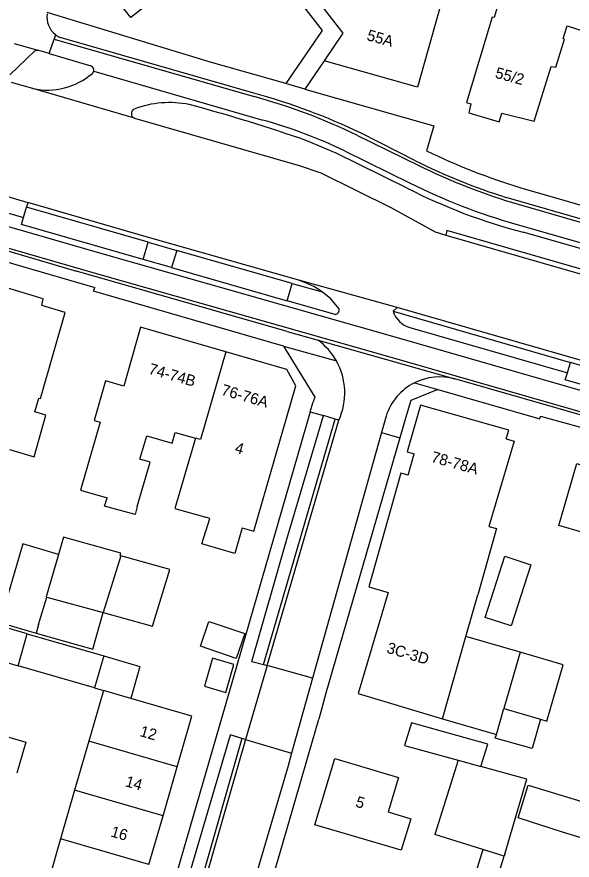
# Model space of a CAD drawing. Extents: x 194485 to 197793, y 468269 to 470822.
# Drawn here: x 195024.7 to 195084.7, y 469884.3 to 469975.4 of the extents above; entities that cross this region are included whole.
import ezdxf

# ---------------------------------------------------------------- set-up
doc = ezdxf.new("R2010")
doc.units = 0
for name, color, linetype in [('BGT grensvlak gebouwinstallatie plus 1', 7, 'Continuous'), ('BGT grensvlak ondersteunend wegdeel', 7, 'Continuous'), ('BGT grensvlak overig bouwwerk uitbreiding populatie', 7, 'Continuous'), ('BGT grensvlak pand op maaiveld', 7, 'Continuous'), ('BGT grensvlak pand op maaiveld LR', 7, 'Continuous'), ('BGT grensvlak vegetatieobject', 7, 'Continuous'), ('BGT grensvlak wegdeel', 7, 'Continuous'), ('BGT tekst huisnummerreeks', 7, 'Continuous')]:
    doc.layers.add(name, color=color, linetype=linetype)

msp = doc.modelspace()

# ---------------------------------------------------------------- linework, layer by layer
at = {"layer": 'BGT grensvlak gebouwinstallatie plus 1'}
for p, q in [((195079.063, 469906.728), (195073.22, 469908.419)), ((195079.063, 469906.728), (195077.314, 469900.655)), ((195083.744, 469905.365), (195079.063, 469906.728)), ((195033.077, 469902.876), (195034.039, 469902.6)), ((195076.507, 469897.852), (195077.314, 469900.655)), ((195077.314, 469900.655), (195081.283, 469899.485)), ((195070.702, 469899.524), (195076.507, 469897.852)), ((195081.283, 469899.485), (195080.37, 469896.314)), ((195076.394, 469897.459), (195076.507, 469897.852)), ((195080.37, 469896.314), (195076.394, 469897.459)), ((195075.06, 469885.416), (195073.14, 469879.238)), ((195075.455, 469878.553), (195077.355, 469884.702))]:
    msp.add_line(p, q, dxfattribs=at)
for points in [[(195029.188, 469917.299), (195025.31, 469918.449), (195022.793, 469909.966), (195026.751, 469908.792)], [(195045.429, 469910.07), (195049.306, 469908.766), (195048.398, 469906.069), (195044.521, 469907.373), (195045.429, 469910.07)], [(195034.07, 469906.329), (195037.981, 469905.202), (195036.987, 469901.746)], [(195081.283, 469899.485), (195081.952, 469899.287), (195083.744, 469905.365)]]:
    msp.add_lwpolyline(points, dxfattribs=at)
at = {"layer": 'BGT grensvlak ondersteunend wegdeel'}
msp.add_line((195025.884, 469955.345), (195025.74, 469954.853), dxfattribs=at)
at = {"layer": 'BGT grensvlak overig bouwwerk uitbreiding populatie'}
for p, q in [((195045.83, 469906.081), (195044.957, 469903.056)), ((195048.134, 469905.417), (195045.83, 469906.081)), ((195047.262, 469902.392), (195048.134, 469905.417)), ((195044.957, 469903.056), (195047.262, 469902.392))]:
    msp.add_line(p, q, dxfattribs=at)
at = {"layer": 'BGT grensvlak pand op maaiveld'}
for p, q in [((195066.959, 469925.863), (195067.612, 469928.194)), ((195049.039, 469920.182), (195048.236, 469917.405)), ((195027.012, 469909.719), (195027.909, 469912.695)), ((195073.22, 469908.419), (195074.498, 469912.933)), ((195034.006, 469911.011), (195038.678, 469909.72)), ((195027.012, 469909.719), (195026.751, 469908.792)), ((195025.811, 469908.71), (195034.07, 469906.329)), ((195070.702, 469899.524), (195073.22, 469908.419)), ((195034.07, 469906.329), (195033.077, 469902.876)), ((195033.077, 469902.876), (195024.828, 469905.258)), ((195034.039, 469902.6), (195032.455, 469897.124)), ((195036.987, 469901.746), (195034.039, 469902.6)), ((195023.547, 469897.627), (195025.638, 469897.003)), ((195025.638, 469897.003), (195024.663, 469893.659)), ((195032.455, 469897.124), (195030.927, 469891.84)), ((195072.368, 469895.064), (195069.871, 469887.028)), ((195040.483, 469889.07), (195042.013, 469894.354)), ((195030.927, 469891.84), (195029.399, 469886.557)), ((195038.953, 469883.787), (195040.483, 469889.07)), ((195083.661, 469887.296), (195078.873, 469888.827)), ((195029.399, 469886.557), (195027.871, 469881.273)), ((195075.06, 469885.416), (195069.871, 469887.028)), ((195077.355, 469884.702), (195075.06, 469885.416)), ((195077.421, 469884.927), (195077.355, 469884.702))]:
    msp.add_line(p, q, dxfattribs=at)
for points in [[(195088.757, 469981.919), (195084.99, 469983.19), (195083.66, 469978.903), (195081.806, 469979.503), (195081.053, 469976.868), (195077.065, 469978.039), (195076.261, 469975.326), (195076.057, 469975.362), (195073.279, 469966.137), (195073.765, 469966.003), (195073.523, 469965.018), (195076.808, 469964.055), (195077.114, 469964.989), (195080.588, 469964.143), (195082.43, 469970.055), (195082.941, 469969.96), (195083.88, 469972.98), (195083.726, 469973.067), (195084.153, 469974.436), (195086.276, 469973.751), (195087.602, 469978.115)], [(195071.918, 469981.777), (195068.001, 469967.805), (195057.878, 469970.659)], [(195056.651, 469977.891), (195059.918, 469973.658), (195057.878, 469970.659)], [(195023.89, 469928.648), (195026.554, 469927.87), (195027.812, 469932.365), (195026.619, 469932.715), (195027.072, 469934.188), (195027.224, 469934.162), (195029.905, 469943.468), (195027.368, 469944.22), (195027.524, 469944.944), (195020.571, 469947.029), (195019.214, 469942.648)], [(195047.263, 469939.204), (195038.062, 469941.864), (195036.235, 469935.501), (195034.252, 469936.059), (195033.026, 469931.79), (195033.681, 469931.606), (195031.574, 469924.241), (195034.428, 469923.416)], [(195049.039, 469920.182), (195050.293, 469919.82), (195054.849, 469935.523), (195053.855, 469937.298), (195047.263, 469939.204)], [(195077.581, 469929.787), (195077.849, 469930.74), (195068.299, 469933.426), (195066.867, 469928.406), (195067.612, 469928.194)], [(195037.691, 469922.473), (195039.082, 469927.286), (195037.987, 469927.603), (195038.72, 469930.139), (195041.458, 469929.348), (195041.791, 469930.5), (195043.981, 469929.867)], [(195043.981, 469929.867), (195041.767, 469922.284), (195045.118, 469921.316)], [(195077.581, 469929.787), (195078.42, 469929.55), (195075.707, 469920.315), (195076.532, 469920.094), (195074.498, 469912.933)], [(195085.187, 469927.13), (195085.897, 469926.885), (195086.355, 469928.042), (195089.172, 469927.301), (195088.836, 469926.259), (195096.525, 469923.95), (195094.499, 469917.185), (195094.219, 469917.276), (195093.857, 469916.133), (195092.6, 469916.344), (195092.938, 469917.613), (195083.269, 469920.439), (195085.187, 469927.13)], [(195066.959, 469925.863), (195066.186, 469926.083), (195062.741, 469913.788), (195064.809, 469913.2), (195061.557, 469902.271), (195070.702, 469899.524)], [(195037.691, 469922.473), (195037.458, 469921.633), (195034.154, 469922.536), (195034.428, 469923.416)], [(195048.236, 469917.405), (195044.672, 469918.441), (195045.524, 469921.193), (195045.118, 469921.316)], [(195035.909, 469917.138), (195035.842, 469917.157), (195035.922, 469917.446), (195029.726, 469919.165), (195029.188, 469917.299)], [(195029.188, 469917.299), (195027.864, 469912.708), (195027.909, 469912.695)], [(195038.678, 469909.72), (195039.344, 469909.536), (195041.202, 469915.67), (195035.909, 469917.138)], [(195077.431, 469917.101), (195080.247, 469916.182), (195078.114, 469909.581), (195075.298, 469910.487), (195077.431, 469917.101)], [(195026.751, 469908.792), (195032.898, 469907.075), (195034.006, 469911.011)], [(195025.811, 469908.71), (195018.643, 469910.802), (195017.65, 469907.372), (195024.828, 469905.258)], [(195042.013, 469894.354), (195043.598, 469899.829), (195036.987, 469901.746)], [(195074.826, 469894.381), (195075.58, 469896.807), (195067.333, 469899.098), (195066.579, 469896.672), (195072.368, 469895.064)], [(195059.05, 469895.264), (195065.914, 469893.179), (195064.814, 469889.485), (195067.25, 469888.734), (195066.227, 469885.331), (195056.876, 469888.078), (195059.05, 469895.264)], [(195077.421, 469884.927), (195079.791, 469893.002), (195074.826, 469894.381)], [(195078.873, 469888.827), (195079.927, 469892.378), (195086.588, 469890.358), (195085.666, 469886.675), (195083.661, 469887.296)]]:
    msp.add_lwpolyline(points, dxfattribs=at)
at = {"layer": 'BGT grensvlak pand op maaiveld LR'}
for p, q in [((195035.909, 469917.138), (195034.006, 469911.011)), ((195027.909, 469912.695), (195034.006, 469911.011)), ((195024.828, 469905.258), (195025.811, 469908.71)), ((195042.013, 469894.354), (195032.455, 469897.124)), ((195072.368, 469895.064), (195074.826, 469894.381)), ((195040.483, 469889.07), (195030.927, 469891.84)), ((195038.953, 469883.787), (195029.399, 469886.557))]:
    msp.add_line(p, q, dxfattribs=at)
msp.add_lwpolyline([(195047.263, 469939.204), (195044.519, 469929.712), (195043.981, 469929.867)], dxfattribs=at)
at = {"layer": 'BGT grensvlak vegetatieobject'}
for p, q in [((195038.863, 469951.07), (195041.957, 469950.16)), ((195054.439, 469946.595), (195057.663, 469945.689)), ((195065.356, 469943.593), (195084.527, 469938.04))]:
    msp.add_line(p, q, dxfattribs=at)
msp.add_lwpolyline([(195146.695, 469930.569), (195071.158, 469952.329), (195071.032, 469951.821)], dxfattribs=at)
at = {"layer": 'BGT grensvlak wegdeel'}
for p, q in [((195045.724, 469970.489), (195027.962, 469975.874)), ((195028.167, 469971.43), (195028.705, 469973.01)), ((195028.842, 469973.487), (195028.705, 469973.01)), ((195028.705, 469973.01), (195050.331, 469966.784)), ((195050.307, 469967.143), (195029.366, 469973.16)), ((195024.404, 469972.54), (195026.941, 469971.803)), ((195028.167, 469971.43), (195026.941, 469971.803)), ((195028.167, 469971.43), (195032.665, 469970.123)), ((195053.768, 469968.186), (195045.724, 469970.489)), ((195057.878, 469970.659), (195055.801, 469967.605)), ((195032.852, 469969.295), (195032.988, 469969.535)), ((195032.988, 469969.535), (195051.262, 469964.251)), ((195026.398, 469967.654), (195024.107, 469968.306)), ((195026.398, 469967.654), (195024.107, 469968.306)), ((195037.397, 469964.467), (195026.398, 469967.654)), ((195037.397, 469964.467), (195026.398, 469967.654)), ((195055.801, 469967.605), (195053.768, 469968.186)), ((195067.775, 469959.854), (195061.881, 469962.823)), ((195061.418, 469962.635), (195068.143, 469959.326)), ((195060.151, 469960.893), (195067.178, 469957.441)), ((195013.563, 469958.908), (195025.884, 469955.345)), ((195077.487, 469955.564), (195154.987, 469933.181)), ((195155.08, 469933.502), (195077.568, 469955.894)), ((195025.412, 469953.731), (195025.74, 469954.853)), ((195038.863, 469951.07), (195025.74, 469954.853)), ((195025.191, 469952.976), (195025.412, 469953.731)), ((195038.336, 469949.187), (195025.191, 469952.976)), ((195078.618, 469953.007), (195154.022, 469931.248)), ((195015.258, 469952.603), (195031.126, 469947.91)), ((195142.46, 469933.909), (195079.392, 469952.147)), ((195015.112, 469951.381), (195033.116, 469946.165)), ((195038.336, 469949.187), (195038.863, 469951.07)), ((195071.032, 469951.821), (195136.439, 469932.999)), ((195071.032, 469951.821), (195136.439, 469932.999)), ((195041.957, 469950.16), (195041.397, 469948.3)), ((195054.439, 469946.595), (195041.957, 469950.16)), ((195041.397, 469948.3), (195038.336, 469949.187)), ((195041.397, 469948.3), (195053.88, 469944.698)), ((195053.904, 469941.399), (195031.126, 469947.91)), ((195053.88, 469944.698), (195054.439, 469946.595)), ((195065.78, 469943.999), (195055.147, 469946.934)), ((195059.084, 469943.234), (195053.88, 469944.698)), ((195065.356, 469943.593), (195065.78, 469943.999)), ((195133.95, 469924.347), (195065.78, 469943.999)), ((195053.904, 469941.399), (195057.233, 469940.46)), ((195067.158, 469941.827), (195084.181, 469936.918)), ((195057.233, 469940.46), (195072.032, 469936.283)), ((195053.517, 469939.827), (195059.222, 469938.217)), ((195084.181, 469936.918), (195084.527, 469938.04)), ((195097.114, 469934.407), (195084.527, 469938.04)), ((195083.952, 469936.176), (195084.181, 469936.918)), ((195067.654, 469935.856), (195070.166, 469935.133)), ((195109.843, 469925.401), (195072.032, 469936.283)), ((195096.601, 469932.525), (195083.952, 469936.176)), ((195056.395, 469932.726), (195056.702, 469933.788)), ((195051.35, 469905.397), (195059.099, 469931.938)), ((195051.738, 469905.298), (195059.483, 469931.826)), ((195056.395, 469932.726), (195057.833, 469932.307)), ((195059.483, 469931.826), (195059.099, 469931.938)), ((195064.587, 469932.234), (195064.103, 469930.479)), ((195066.809, 469932.408), (195066.081, 469929.902)), ((195064.103, 469930.479), (195056.647, 469903.914)), ((195064.103, 469930.479), (195066.081, 469929.902)), ((195050.082, 469905.722), (195051.35, 469905.397)), ((195051.35, 469905.397), (195051.738, 469905.298)), ((195051.738, 469905.298), (195049.379, 469897.299)), ((195056.647, 469903.914), (195051.738, 469905.298)), ((195056.647, 469903.914), (195054.376, 469895.822)), ((195028.462, 469832.157), (195047.759, 469897.79)), ((195048.996, 469897.415), (195029.694, 469829.948)), ((195049.379, 469897.299), (195030.079, 469829.841)), ((195048.996, 469897.415), (195047.759, 469897.79)), ((195049.379, 469897.299), (195048.996, 469897.415)), ((195049.379, 469897.299), (195054.376, 469895.822))]:
    msp.add_line(p, q, dxfattribs=at)
for points in [[(195047.765, 469983.79), (195036.998, 469975.347), (195033.81, 469979.356)], [(195047.765, 469983.79), (195051.305, 469979.229), (195052.732, 469980.299), (195057.685, 469973.917), (195053.768, 469968.186)], [(195154.936, 469915.078), (195108.391, 469928.45), (195065.323, 469940.871), (195033.663, 469949.858), (194955.95, 469972.298), (194924.809, 469981.245)], [(195153.94, 469913.042), (195064.287, 469938.858), (195033.432, 469947.603), (195000, 469957.257), (194956.182, 469969.939), (194926.844, 469978.413)], [(195023.908, 469969.121), (195026.64, 469971.737), (195026.941, 469971.803)], [(195055.801, 469967.605), (195069.745, 469963.613), (195068.971, 469960.939)], [(195037.397, 469964.467), (195055.21, 469959.345), (195057.531, 469958.546), (195065.163, 469954.755), (195069.879, 469952.153), (195071.032, 469951.821)], [(195037.397, 469964.467), (195055.21, 469959.345), (195057.531, 469958.546), (195065.163, 469954.755), (195069.879, 469952.153), (195071.032, 469951.821)], [(195066.878, 469956.892), (195059.185, 469960.671), (195056.039, 469962.008)], [(195013.563, 469958.908), (195013.083, 469958.498), (195012.893, 469957.651), (195013.116, 469957.269), (195025.412, 469953.731)], [(195079.14, 469956.933), (195110.953, 469947.771), (195133.317, 469941.331)], [(195055.147, 469946.934), (195038.92, 469951.576), (195025.884, 469955.345)], [(195053.517, 469939.827), (195032.975, 469945.742), (195033.116, 469946.165)], [(195059.477, 469943.881), (195058.626, 469944.935), (195057.663, 469945.689)], [(195053.517, 469939.827), (195056.883, 469934.316), (195056.702, 469933.788)], [(195070.166, 469935.133), (195067.267, 469933.935), (195066.809, 469932.408)], [(195070.166, 469935.133), (195081.188, 469931.975), (195081.289, 469932.247), (195100.523, 469926.945)], [(195056.395, 469932.726), (195047.599, 469902.294), (195038.424, 469870.737), (195032.714, 469851.18)], [(195050.082, 469905.722), (195053.873, 469918.963), (195057.833, 469932.307)], [(195059.099, 469931.938), (195058.305, 469932.169), (195057.833, 469932.307)], [(195066.081, 469929.902), (195058.062, 469902.3), (195057.302, 469899.492)], [(195042.1, 469847.554), (195048.043, 469867.833), (195053.126, 469885.096), (195057.302, 469899.492)], [(195054.376, 469895.822), (195053.996, 469894.471), (195041.982, 469853.568), (195034.604, 469828.587)]]:
    msp.add_lwpolyline(points, dxfattribs=at)
for centre, radius, start, end in [((195030.415, 469975.422), 2.493, 172.745, 230.90172), ((195030.408, 469975.412), 2.482, 230.88488, 245.18301), ((195032.491, 469969.645), 0.509, 347.54009, 70.02163), ((195027.954, 469975.046), 7.554, 258.11104, 310.42053), ((195032.899, 469902.839), 66.619, 64.21172, 74.85206), ((195033.07, 469903.772), 65.334, 64.28517, 74.68092), ((195041.181, 469955.317), 10.822, 78.61471, 110.73458), ((194996.215, 469790.415), 181.723, 70.77955, 74.97765), ((195037.585, 469964.963), 0.531, 116.42957, 249.22468), ((195037.168, 469913.499), 52.672, 64.12979, 74.48006), ((195098.865, 470021.915), 67.91, 243.88273, 253.11411), ((195096.056, 470015.703), 62.601, 243.14322, 252.82287), ((195099.106, 470022.746), 70.574, 243.97741, 252.16204), ((195096.874, 470017.084), 66.627, 243.53138, 254.09721), ((195094.19, 470010.048), 59.763, 242.80554, 255.66347), ((195052.289, 469937.994), 9.386, 55.0718, 72.27275), ((195059.032, 469943.709), 0.477, 276.28244, 21.16699), ((195067.828, 469944.313), 2.575, 196.23943, 254.91673), ((195053.064, 469934.76), 7.062, 29.31136, 53.81922), ((195053.074, 469934.765), 7.051, 335.36522, 29.31195), ((195070.42, 469930.15), 6.341, 75.27664, 115.86459), ((195070.4, 469930.421), 6.089, 116.80657, 162.6796)]:
    msp.add_arc(centre, radius, start, end, dxfattribs=at)

# ---------------------------------------------------------------- texts
at = {"layer": 'BGT tekst huisnummerreeks'}
for s, rotation, p in [('55A', 344.3, (195062.426, 469972.908)), ('55/2', 344.7, (195076.297, 469968.839)), ('74-74B', 343.9, (195038.832, 469936.851)), ('76-76A', 343.9, (195046.684, 469934.581)), ('4', 343.8, (195048.153, 469928.328)), ('78-78A', 344.2, (195069.373, 469927.327)), ('3C-3D', 343.4, (195064.568, 469906.699)), ('12', 343.9, (195037.89, 469897.685)), ('14', 343.9, (195036.317, 469892.267)), ('5', 343.2, (195061.204, 469890.064)), ('16', 343.8, (195034.741, 469886.839))]:
    msp.add_text(s, height=1.2, rotation=rotation, dxfattribs=at).set_placement(p)

doc.saveas('drawing.dxf')
